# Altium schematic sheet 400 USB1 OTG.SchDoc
size Letter; Organization: Toradex Solutions Inc.; Address1: 6415 Northwest Drive; Address2: Mississauga, ON, L4V 1X1; Address3: Canada
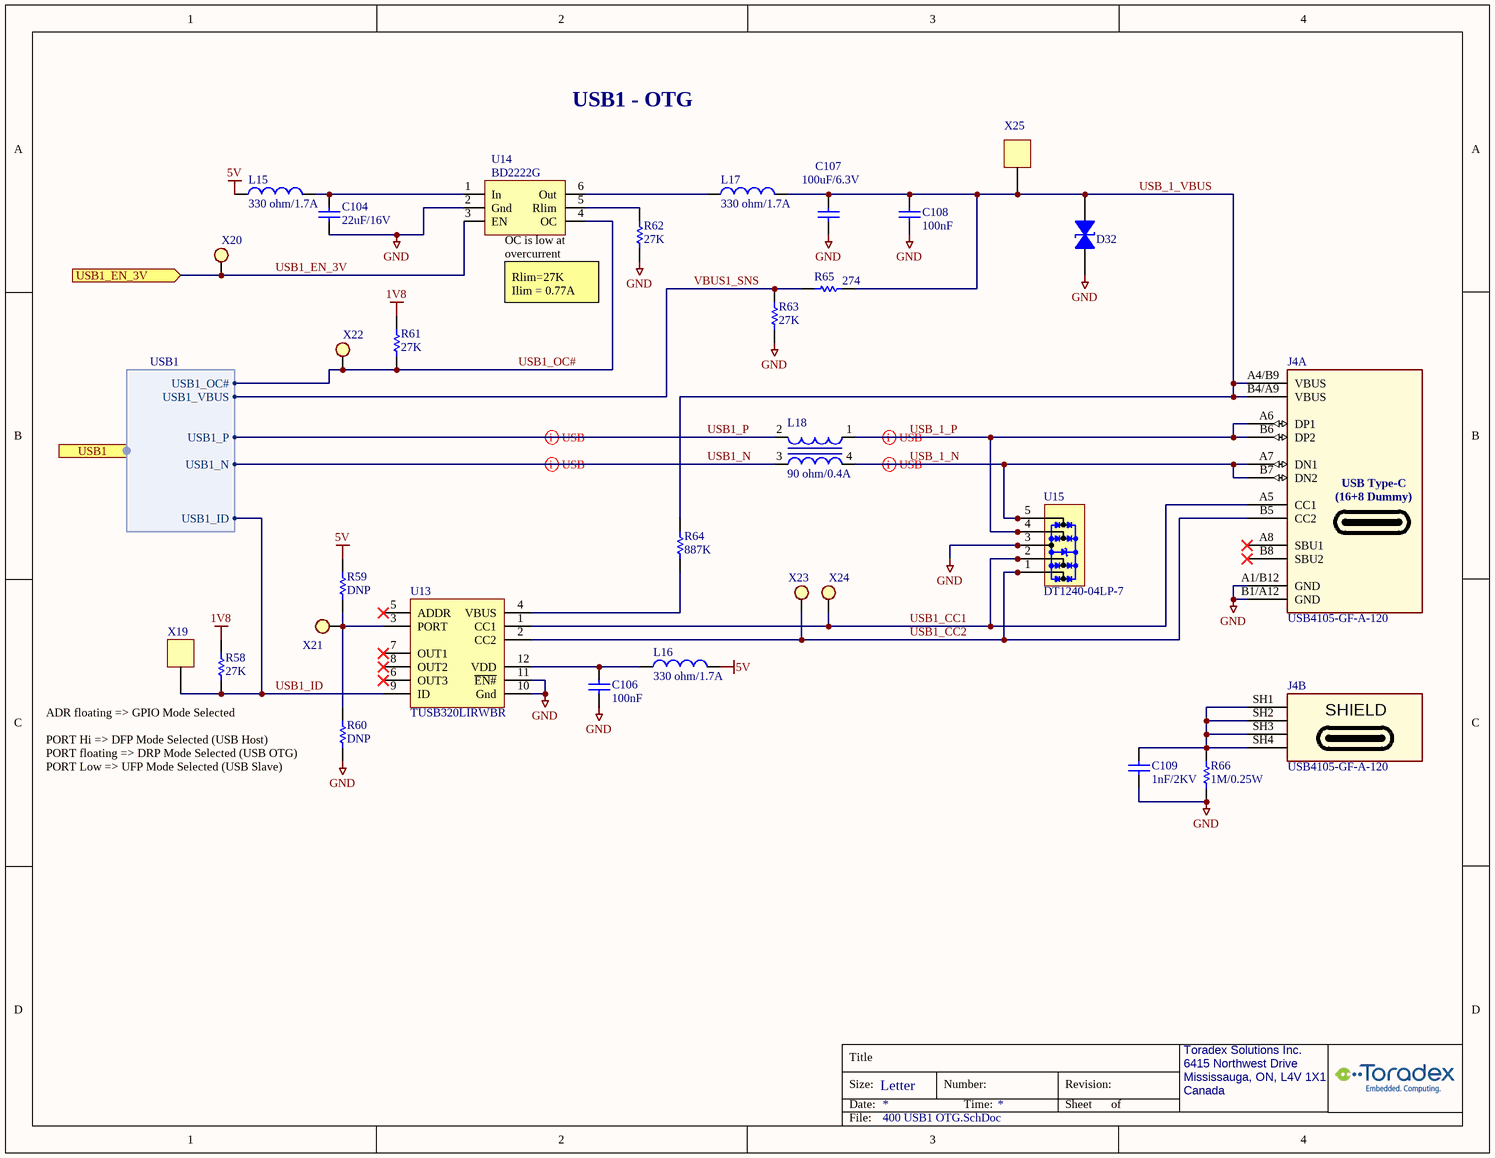
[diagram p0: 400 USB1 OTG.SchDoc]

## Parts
C104  value 22uF/16V  [C/0805]  (hidden comment: 1314-Cap-0805-22uF/16V)
C106  100nF  [C0402_CAPC1005L]
C107  value 100uF/6.3V  [C/1206]  (hidden comment: 0455-Cap-1206-100uF/6.3V)
C108  100nF  [C0402_CAPC1005L]
C109  value 1nF/2KV  [C/1206]  (hidden comment: 0567-Cap-1206-1nF/2KV)
D32  D5V0L1B2S9-7  [SOD923_DIO]  (value not drawn)
J4  USB4105-GF-A-120  [GCT_USB4105GFA120]  (parts A,B of 2)
L15  value 330 ohm/1.7A  [INDC1608x095]  (hidden comment: 0405-Fer-0603-330ohm/1.7A)
L16  value 330 ohm/1.7A  [INDC1608x095]  (hidden comment: 0405-Fer-0603-330ohm/1.7A)
L17  value 330 ohm/1.7A  [INDC1608x095]  (hidden comment: 0405-Fer-0603-330ohm/1.7A)
L18  90 ohm/0.4A  [COMMON_CHOKE_BOURNS_SRF2012-900YA]
R58  value 27K  [R0402_RESC1005L]  (hidden comment: 1538-Res-0402-27k)
R59  value DNP  [R/0603]  (hidden comment: 0000-Res-0603-DNP)
R60  value DNP  [R/0603]  (hidden comment: 0000-Res-0603-DNP)
R61  value 27K  [R0402_RESC1005L]  (hidden comment: 1538-Res-0402-27k)
R62  value 27K  [R0402_RESC1005L]  (hidden comment: 1538-Res-0402-27k)
R63  value 27K  [R0402_RESC1005L]  (hidden comment: 1538-Res-0402-27k)
R64  value 887K  [R0402_RESC1005L]  (hidden comment: 1809-Res-0402-887K)
R65  value 274  [R/0603]  (hidden comment: 0728-Res-0603-274ohm)
R66  value 1M/0.25W  [R/1206]  (hidden comment: 1860-Res-1206-1M-5%-0.25W)
U13  TUSB320LIRWBR  [QFN40P160X160X40-12N]
U14  BD2222G  [sot23-6]
U15  DT1240-04LP-7  [10-UFDFN]
X19  000-TestPoint  [TestPoint_1]  (value not drawn)
X20  000-TestPoint2  [TestPoint_3]  (value not drawn)
X21  000-TestPoint2  [TestPoint_3]  (value not drawn)
X22  000-TestPoint2  [TestPoint_3]  (value not drawn)
X23  000-TestPoint2  [TestPoint_3]  (value not drawn)
X24  000-TestPoint2  [TestPoint_3]  (value not drawn)
X25  000-TestPoint  [TestPoint_1]  (value not drawn)

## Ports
USB1 (harness USB1), USB1_EN_3V (in)

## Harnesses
USB1: USB1_N, USB1_P, USB1_ID, USB1_VBUS, USB1_OC#

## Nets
1V8: R58.2 R61.2
5V: L15.1 L16.1 R59.2
GND: C104.1 C106.1 C107.1 C108.1 C109.1 D32.2 J4.A1/B12(GND) J4.B1/A12(GND) R60.1 R62.1 R63.1 R66.2 U13.10(Gnd) U13.11(~{EN#}) U14.2(Gnd) U15.3(GND) U15.8(GND)
USB1_CC1: J4.A5(CC1) U13.1(CC1) U15.2(IO2) U15.9(NC) X24.1
USB1_CC2: J4.B5(CC2) U13.2(CC2) U15.1(IO1) U15.10(NC) X23.1
USB1_EN_3V: U14.3(EN) X20.1 ; port USB1_EN_3V
USB1_ID: R58.1 U13.9(ID) X19.1 ; port USB1.USB1_ID
USB1_N: L18.3 ; port USB1.USB1_N
USB1_OC#: R61.1 U14.4(OC) X22.1 ; port USB1.USB1_OC#
USB1_P: L18.2 ; port USB1.USB1_P
USB_1_N: J4.A7(DN1) J4.B7(DN2) L18.4 U15.5(IO4) U15.6(NC)
USB_1_P: J4.A6(DP1) J4.B6(DP2) L18.1 U15.4(IO3) U15.7(NC)
USB_1_VBUS: C107.2 C108.2 D32.1 J4.A4/B9(VBUS) J4.B4/A9(VBUS) L17.2 R64.1 R65.1 X25.1
VBUS1_SNS: R63.2 R65.2 ; port USB1.USB1_VBUS
NetC104_2: C104.2 L15.2 U14.1(In)
NetC106_2: C106.2 L16.2 U13.12(VDD)
NetC109_2: C109.2 J4.SH1(SHIELD) J4.SH2(SHIELD) J4.SH3(SHIELD) J4.SH4(SHIELD) R66.1
NetL17_1: L17.1 U14.6(Out)
NetR59_1: R59.1 R60.2 U13.3(PORT) X21.1
NetR62_2: R62.2 U14.5(Rlim)
NetR64_2: R64.2 U13.4(VBUS)

Not connected (* = marked no-connect by the designer): J4 A8(SBU1)* B8(SBU2)*; U13 5(ADDR)* 6(OUT3)* 7(OUT1)* 8(OUT2)*

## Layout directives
differential pair; differential pair class USB: USB1_N, USB1_P, USB_1_N, USB_1_P

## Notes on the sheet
- USB1 - OTG
- (near U14) OC is low at
- (near U14) overcurrent
- Rlim=27K
  Ilim = 0.77A
- ADR floating => GPIO Mode Selected
- PORT Hi => DFP Mode Selected (USB Host)
- (near R60) PORT floating => DRP Mode Selected (USB OTG)
- (near R60) PORT Low => UFP Mode Selected (USB Slave)

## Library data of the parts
C104 = 1314-Cap-0805-22uF/16V: (-55 to 85 DegC) CAP CER 22uF 16V X5R 0805; Mfr: Samsung; MfrNo: CL21A226MOQNNNE; PN: 1314; Alt: CL21A226MOCLRNC,CL21A226KOQNNNG,GRM21BR61C226ME44L,EMK212BBJ226MG-T
C106 C108 = 1566-Cap-0402-100nF/50V: (-55 to 125 DegC AEC) Cap Ceramic 0.1uF 50V X7R 10% 0402; MfrNo: GRT155R71H104KE01D; Mfr: Murata; Alt: CL05B104KB54PNC,GCM155R71H104ME02D,GCM155R71H104KE02D,GCM155R71H104KE02J; PN: 1566
C107 = 0455-Cap-1206-100uF/6.3V: (-55 to 85 DegC) CAP CER 100UF 6.3V X5R 1206; MfrNo: CC1206MKX5R5BB107; Mfr: Yageo; PN: 455; Alt: 490-7217-1-ND; Alt2: 490-4539-1-ND; DR: 311-1991-6-ND; TR: 311-1991-2-ND
C109 = 0567-Cap-1206-1nF/2KV: CAP CER 1000PF 2KV X7R 1206; Mfr: Johanson Dielectrics Inc.; MfrNo: 202R18W102KV4E; PN: 567; Alt: 478-2956-1-ND; Alt2: 399-4819-1-ND
D32 = 1655-D5V0L1B2S9-7: (-65 to 155 DegC) TVS DIODE Vwm:5V Vcl:14V@6A SOD-923; Mfr: Diodes; PN: 1655
J4 = 1660-Conn-USB-Type-C: (-40 to 85 DegC) Conn USB TYPE C RA, 24 (16+8 Dummy) Position, SMT/TH; Mfr: Global Connector Technology; Desc: (-40 to 85 DegC) Conn USB TYPE C RA SMT/TH; PN: 1660
L15-L17 = 0405-Fer-0603-330ohm/1.7A: (-55 to 125 DegC) FERRITE BEAD 330 OHM 0603 1.7A 80mohm, typ 48mohm; Mfr: TDK Corporation; MfrNo: MPZ1608S331ATA00; PN: 405; TR: 445-5221-2-ND; DR: 445-5221-6-ND; DR2: 810-MPZ1608S331ATA00
L18 = 0277-Ind-2x1.2-90ohm/0.4A-Choke: INDUCTOR COMMON MODE 90 OHM 0.4A 0.3ohm; MfrNo: SRF2012-900YA; Mfr: Bourns Inc.; PN: 277; Alt: 445-2207-1-ND
R58 R61-R63 = 1538-Res-0402-27k: (-55 to 155 DegC AEC) RES 27K OHM 1% 1/16W 100ppm 0402; Mfr: Stackpole Electronics; MfrNo: RMCF0402FT27K0; PN: 1538; Alt: AC0402FR-0727KL,CRGCQ0402F27K
R59 R60 = 0000-Res-0603-DNP: RES 0603
R64 = 1809-Res-0402-887K: (-55 to 155 DegC AEC) RES 887K OHM 1% 1/16W 100ppm 0402; MfrNo: RMCF0402FT887K; Mfr: Stackpole Electronics; PN: 1809
R65 = 0728-Res-0603-274ohm: RES SMD 274 OHM 1% 1/10W 0603; MfrNo: RC0603FR-07274RL; Mfr: Yageo; PN: 728; TR: 311-274HRTR-ND
R66 = 1860-Res-1206-1M-5%-0.25W: (-55 to 155 DegC) RES SMD 1M OHM 5% 0.25W 10ppm 1206; Mfr: TE Connectivity; MfrNo: CRGCQ1206J1M0; PN: 1860; Alt: RMCF1206JT1M00, RMCF1206JG1M00, CR1206-JW-105ELF
U13 = 1458-TUSB320LI: (-40 to 85 DegC) IC USB TYPE-C CC LOGIC AND PORT Control 12-X2QFN; Mfr: Texas Instruments; PN: 1458
U14 = 1469-BD2222G: (-40 to 85 DegC) IC PWR SWITCH 2.8-5.5V EN-Active-High ENth:2.0V No-Discharge 89mohm typ ADJ 0.2-1.7A 6SSOP; Mfr: Rohm; MfrNo: BD2222G-GTR; PN: 1469; Note: Similar BD2242G, TPS25221, TPS2553, AP22653, RT9728A, RT9728B, RT9728C, AP2553, MIC2009YM6, MIC2019YM6, MIC2009A-1YM6,MIC2019A-1YM6
U15 = 1657-DT1240-04LP-7: (-55 to 85 DegC) IC TVS DIODE 4ch Vrm:5.5V Vcl:11V@5.5A 10-UFDFN 0.5mm; Mfr: Diodes; PN: 1657
X19 X25 = 000-TestPoint: Note: this is PCB footprint only, no parts to buy or assemble
X20-X24 = 000-TestPoint2: TestPoint SMD; Note: PCB footprint only, no parts to buy or assemble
